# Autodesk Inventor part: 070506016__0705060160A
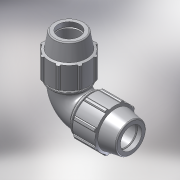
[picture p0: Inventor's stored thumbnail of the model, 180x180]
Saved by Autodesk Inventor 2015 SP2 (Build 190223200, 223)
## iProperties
Created: 2017-02
Part Number: 070506016__0705060160A
Material: PVC-Piping
Description: PLASSON 90° ELBOW 16-16
Document SubType Name: Modeling
Designer: KIM
Mass: 92.6774 g
Surface Area: 199.44 cm^2
Volume: 66.1981 cm^3
Density: 1.4 g/cm^3
Appearance: Smooth - White
Author: KIM
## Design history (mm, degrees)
derived "07050.ipt"
feature "Solid1::07050.ipt"
tag "TaggingFeature1"
body "Solid1"
other parameters: "d2" = 16, "d4" = 5.25, "d5" = 15.75, "d7" = 39, "d9" = 9, "d11" = 2.1, "d13" = 120 deg, "d14" = 24, "d15" = 12 deg, "d16" = 33.93, "d18" = 0.8, "d19" = 35 deg, "d20" = 17.5 deg, "d21" = 36.27, "d23" = 0, "d25" = 360 deg, "d27" = 0.78, "d33" = 0.32, "d42" = 23.31, "d43" = 1.17, "d46" = 0.48, "d51" = 63, "d59" = 90 deg, "d64" = 14.4, "d67" = 29.25, "d68" = 2.1, "d70" = 90 deg, "d71" = 2.4, "d_" = 16, "E_" = 39, "A_" = 63
